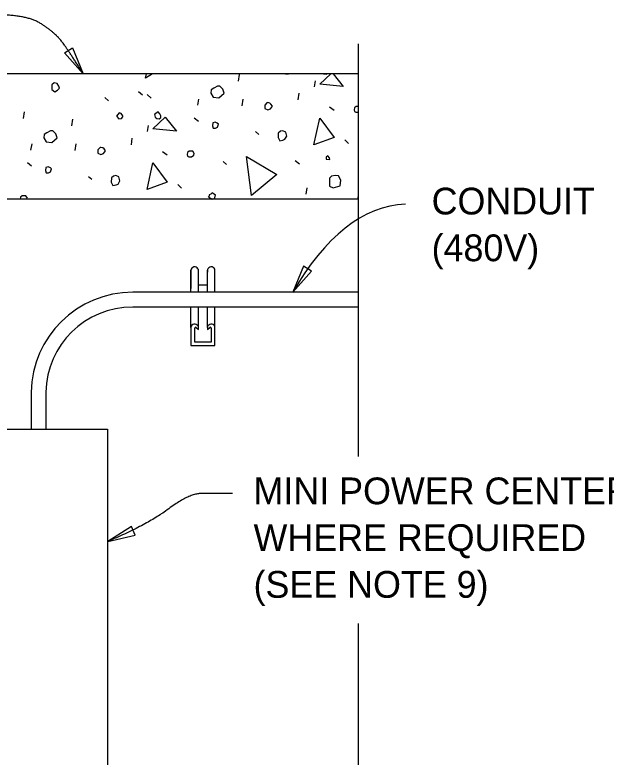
# Model space of a CAD drawing. Extents: x -1660015.2 to -1659984.9, y 2580594.2 to 2580616.7.
# Drawn here: x -1659999.271 to -1659995.935, y 2580610.338 to 2580614.529 of the extents above; entities that cross this region are included whole.
import ezdxf

# ---------------------------------------------------------------- set-up
doc = ezdxf.new("R2010")
doc.units = 0
for name, color, linetype in [('Default', 7, 'Continuous'), ('Miscellaneous', 7, 'Continuous'), ('Miscellaneous3', 7, 'Continuous'), ('SheetLines_dp', 7, 'Continuous')]:
    doc.layers.add(name, color=color, linetype=linetype)

msp = doc.modelspace()

# ---------------------------------------------------------------- linework, layer by layer
at = {"layer": 'Default'}
for p, q in [((-1659998.2775, 2580612.9626), (-1659998.2775, 2580613.0876)), ((-1659998.2775, 2580613.0876), (-1659998.2775, 2580612.985)), ((-1659998.2359, 2580613.092), (-1659998.238, 2580613.0958)), ((-1659998.2359, 2580613.0759), (-1659998.2359, 2580613.092)), ((-1659998.2359, 2580612.9626), (-1659998.2359, 2580613.0876)), ((-1659998.1816, 2580613.0958), (-1659998.1837, 2580613.092)), ((-1659998.1837, 2580613.092), (-1659998.1837, 2580613.0759)), ((-1659998.1837, 2580612.9626), (-1659998.1837, 2580613.0876)), ((-1659998.1421, 2580612.9626), (-1659998.1421, 2580613.0876)), ((-1659998.1837, 2580613.0037), (-1659998.2359, 2580613.0037)), ((-1659997.3318, 2580612.9626), (-1659998.6065, 2580612.9626)), ((-1659997.3318, 2580612.8794), (-1659998.6065, 2580612.8794)), ((-1659998.2775, 2580612.7647), (-1659998.2775, 2580612.8794)), ((-1659998.2359, 2580612.7647), (-1659998.2359, 2580612.8794)), ((-1659998.1837, 2580612.7647), (-1659998.1837, 2580612.8794)), ((-1659998.1421, 2580612.7647), (-1659998.1421, 2580612.8794)), ((-1659998.2359, 2580612.7691), (-1659998.238, 2580612.7729)), ((-1659998.2359, 2580612.753), (-1659998.2359, 2580612.7691)), ((-1659998.1816, 2580612.7729), (-1659998.1837, 2580612.7691)), ((-1659998.1837, 2580612.7691), (-1659998.1837, 2580612.753)), ((-1659998.2775, 2580612.7647), (-1659998.2775, 2580612.6621)), ((-1659998.2567, 2580612.6808), (-1659998.2567, 2580612.7604)), ((-1659998.2478, 2580612.7637), (-1659998.2359, 2580612.753)), ((-1659998.1837, 2580612.753), (-1659998.1718, 2580612.7637)), ((-1659998.1629, 2580612.7604), (-1659998.1629, 2580612.6808)), ((-1659998.1421, 2580612.6621), (-1659998.1421, 2580612.7647)), ((-1659998.2775, 2580612.6621), (-1659998.1421, 2580612.6621)), ((-1659998.1629, 2580612.6808), (-1659998.2567, 2580612.6808)), ((-1659999.1793, 2580612.3993), (-1659999.1793, 2580612.1902)), ((-1659999.096, 2580612.3985), (-1659999.096, 2580612.1902))]:
    msp.add_line(p, q, dxfattribs=at)
msp.add_lwpolyline([(-1659999.6133, 2580609.4652), (-1659999.7488, 2580609.4652), (-1659999.7488, 2580612.1902), (-1659998.7488, 2580612.1902), (-1659998.7488, 2580609.4652), (-1659998.8843, 2580609.4652)], dxfattribs=at)
for radius, end in [(0.5729, 179.0565), (0.4896, 178.9794)]:
    msp.add_arc((-1659998.6065, 2580612.3898), radius, 90, end, dxfattribs=at)
for centre, major_axis, start_param, end_param in [((-1659998.2567, 2580613.0876), (-0.0208, 0), 3.598509, 6.283184), ((-1659998.1629, 2580613.0876), (0.0208, 0), 0.000002, 2.684677), ((-1659998.2567, 2580612.7647), (-0.0208, 0), 3.598509, 6.283184), ((-1659998.1629, 2580612.7647), (0.0208, 0), 0.000002, 2.684677), ((-1659998.2515, 2580612.7604), (-0.0052, 0), 3.926991, 6.283185), ((-1659998.1681, 2580612.7604), (0.0052, 0), 6.283185, 8.63938)]:
    msp.add_ellipse(centre, major_axis=major_axis, ratio=0.8951, start_param=start_param, end_param=end_param, dxfattribs=at)
at = {"layer": 'Miscellaneous'}
for p, q in [((-1659998.281, 2580614.1961), (-1659998.2809, 2580614.197)), ((-1659998.0087, 2580614.1552), (-1659998.0032, 2580614.1929)), ((-1659997.5806, 2580614.1224), (-1659997.5745, 2580614.1577)), ((-1659998.5729, 2580614.0972), (-1659998.5519, 2580614.077)), ((-1659998.5241, 2580614.0792), (-1659998.5031, 2580614.059)), ((-1659997.6721, 2580614.0487), (-1659997.6667, 2580614.0864)), ((-1659998.7627, 2580614.0619), (-1659998.7424, 2580614.044)), ((-1659998.2386, 2580614.0186), (-1659998.2325, 2580614.0538)), ((-1659997.9893, 2580614.0155), (-1659997.9839, 2580614.0532)), ((-1659997.4962, 2580614.0104), (-1659997.4704, 2580613.9915)), ((-1659999.2228, 2580613.9438), (-1659999.2174, 2580613.9815)), ((-1659998.2587, 2580613.9485), (-1659998.2353, 2580613.9289)), ((-1659998.9504, 2580613.9029), (-1659998.945, 2580613.9406)), ((-1659998.5224, 2580613.8701), (-1659998.5163, 2580613.9053)), ((-1659997.9141, 2580613.87), (-1659997.8944, 2580613.8545)), ((-1659998.6139, 2580613.7964), (-1659998.6085, 2580613.834)), ((-1659997.41, 2580613.8239), (-1659997.389, 2580613.8036)), ((-1659999.1804, 2580613.7662), (-1659999.1743, 2580613.8015)), ((-1659998.9311, 2580613.7631), (-1659998.9257, 2580613.8008)), ((-1659998.438, 2580613.7581), (-1659998.4122, 2580613.7391)), ((-1659999.2004, 2580613.6961), (-1659999.1771, 2580613.6765)), ((-1659998.0969, 2580613.702), (-1659998.0765, 2580613.6841)), ((-1659997.6894, 2580613.7076), (-1659997.6661, 2580613.688)), ((-1659998.8559, 2580613.6176), (-1659998.8362, 2580613.6022)), ((-1659998.3518, 2580613.5715), (-1659998.3308, 2580613.5513)), ((-1659997.628, 2580613.517), (-1659997.6219, 2580613.5523))]:
    msp.add_line(p, q, dxfattribs=at)
for points in [[(-1659998.5335, 2580614.1725), (-1659998.5282, 2580614.197)], [(-1659998.4953, 2580614.197), (-1659998.5335, 2580614.1725)], [(-1659997.744, 2580614.197), (-1659997.7425, 2580614.1955), (-1659997.7274, 2580614.197), (-1659997.7273, 2580614.197)], [(-1659997.5511, 2580614.1381), (-1659997.4877, 2580614.197)], [(-1659997.4755, 2580614.197), (-1659997.4181, 2580614.1245), (-1659997.5511, 2580614.1381)], [(-1659997.5291, 2580614.197), (-1659997.5278, 2580614.1961), (-1659997.5145, 2580614.1945), (-1659997.5116, 2580614.197)], [(-1659999.0621, 2580614.1266), (-1659999.0624, 2580614.1084), (-1659999.0458, 2580614.0947), (-1659999.0302, 2580614.1041), (-1659999.0201, 2580614.1146), (-1659999.0233, 2580614.1266), (-1659999.0327, 2580614.1422), (-1659999.0491, 2580614.1456), (-1659999.0617, 2580614.1345), (-1659999.0621, 2580614.1266)], [(-1659998.1664, 2580614.0871), (-1659998.1527, 2580614.0649), (-1659998.1205, 2580614.0606), (-1659998.0912, 2580614.0865), (-1659998.0977, 2580614.1107), (-1659998.1149, 2580614.1268), (-1659998.1276, 2580614.1259), (-1659998.1481, 2580614.1153), (-1659998.1637, 2580614.1059), (-1659998.1664, 2580614.0871)], [(-1659997.8608, 2580614.0188), (-1659997.8611, 2580614.0006), (-1659997.8434, 2580613.9925), (-1659997.8296, 2580613.9988), (-1659997.8183, 2580614.0147), (-1659997.8264, 2580614.0255), (-1659997.8331, 2580614.0314), (-1659997.8441, 2580614.0337), (-1659997.8489, 2580614.0324), (-1659997.8608, 2580614.0188)], [(-1659997.3318, 2580614.012), (-1659997.3465, 2580614.0117), (-1659997.3548, 2580614.0043), (-1659997.3571, 2580613.9934), (-1659997.3545, 2580613.9837)], [(-1659998.6985, 2580613.9575), (-1659998.6843, 2580613.9431), (-1659998.6692, 2580613.9446), (-1659998.6614, 2580613.9544), (-1659998.6627, 2580613.9593), (-1659998.6714, 2580613.9725), (-1659998.683, 2580613.9771), (-1659998.6908, 2580613.9673), (-1659998.6985, 2580613.9575)], [(-1659998.4929, 2580613.8857), (-1659998.4224, 2580613.9512), (-1659998.3599, 2580613.8722), (-1659998.4929, 2580613.8857)], [(-1659998.4795, 2580613.9514), (-1659998.4696, 2580613.9437), (-1659998.4563, 2580613.9421), (-1659998.4479, 2580613.9495), (-1659998.4481, 2580613.9598), (-1659998.4537, 2580613.9713), (-1659998.4618, 2580613.9821), (-1659998.475, 2580613.9733), (-1659998.4833, 2580613.9659), (-1659998.4795, 2580613.9514)], [(-1659997.5836, 2580613.7955), (-1659997.5515, 2580613.9464), (-1659997.4702, 2580613.8362), (-1659997.5836, 2580613.7955)], [(-1659997.3545, 2580613.9837), (-1659997.3484, 2580613.9802), (-1659997.3326, 2580613.9792), (-1659997.3318, 2580613.9799)], [(-1659998.156, 2580613.9035), (-1659998.1522, 2580613.889), (-1659998.1394, 2580613.8898), (-1659998.128, 2580613.8955), (-1659998.1222, 2580613.9126), (-1659998.129, 2580613.9185), (-1659998.1406, 2580613.9232), (-1659998.1551, 2580613.9193), (-1659998.156, 2580613.9035)], [(-1659999.1082, 2580613.8347), (-1659999.0945, 2580613.8125), (-1659999.0622, 2580613.8082), (-1659999.033, 2580613.8342), (-1659999.0394, 2580613.8583), (-1659999.0567, 2580613.8744), (-1659999.0694, 2580613.8736), (-1659999.0899, 2580613.8629), (-1659999.1055, 2580613.8536), (-1659999.1082, 2580613.8347)], [(-1659997.7848, 2580613.8606), (-1659997.7862, 2580613.837), (-1659997.7762, 2580613.8189), (-1659997.7587, 2580613.821), (-1659997.7472, 2580613.8267), (-1659997.7366, 2580613.8451), (-1659997.7424, 2580613.8668), (-1659997.7602, 2580613.875), (-1659997.7722, 2580613.8718), (-1659997.7848, 2580613.8606)], [(-1659998.8026, 2580613.7665), (-1659998.8029, 2580613.7483), (-1659998.7852, 2580613.7401), (-1659998.7713, 2580613.7464), (-1659998.7601, 2580613.7624), (-1659998.7681, 2580613.7731), (-1659998.7749, 2580613.7791), (-1659998.7859, 2580613.7813), (-1659998.7907, 2580613.78), (-1659998.8026, 2580613.7665)], [(-1659998.2963, 2580613.7313), (-1659998.2901, 2580613.7278), (-1659998.2743, 2580613.7269), (-1659998.2618, 2580613.738), (-1659998.2589, 2580613.7465), (-1659998.2676, 2580613.7597), (-1659998.2882, 2580613.7594), (-1659998.2966, 2580613.752), (-1659998.2988, 2580613.741), (-1659998.2963, 2580613.7313)], [(-1659997.5155, 2580613.7154), (-1659997.4943, 2580613.7133), (-1659997.4968, 2580613.723), (-1659997.5049, 2580613.7337), (-1659997.5157, 2580613.7257), (-1659997.5155, 2580613.7154)], [(-1659998.5253, 2580613.5431), (-1659998.4933, 2580613.6941), (-1659998.412, 2580613.5839), (-1659998.5253, 2580613.5431)], [(-1659997.9365, 2580613.5094), (-1659997.9645, 2580613.7297), (-1659997.7924, 2580613.6282), (-1659997.9365, 2580613.5094)], [(-1659999.0978, 2580613.6512), (-1659999.0939, 2580613.6367), (-1659999.0812, 2580613.6375), (-1659999.0698, 2580613.6431), (-1659999.064, 2580613.6602), (-1659999.0708, 2580613.6662), (-1659999.0824, 2580613.6708), (-1659999.0969, 2580613.6669), (-1659999.0978, 2580613.6512)], [(-1659998.7266, 2580613.6083), (-1659998.728, 2580613.5846), (-1659998.718, 2580613.5666), (-1659998.7004, 2580613.5687), (-1659998.689, 2580613.5743), (-1659998.6784, 2580613.5927), (-1659998.6842, 2580613.6145), (-1659998.7019, 2580613.6226), (-1659998.714, 2580613.6194), (-1659998.7266, 2580613.6083)], [(-1659997.4967, 2580613.6065), (-1659997.4954, 2580613.5629), (-1659997.4746, 2580613.5529), (-1659997.4625, 2580613.5562), (-1659997.4359, 2580613.5633), (-1659997.4316, 2580613.5955), (-1659997.446, 2580613.6201), (-1659997.4648, 2580613.6228), (-1659997.4842, 2580613.6177), (-1659997.4967, 2580613.6065)], [(-1659998.1771, 2580613.4993), (-1659998.1588, 2580613.4887), (-1659998.1443, 2580613.4925), (-1659998.1391, 2580613.512), (-1659998.1582, 2580613.5251), (-1659998.1665, 2580613.5176), (-1659998.1755, 2580613.5126), (-1659998.1771, 2580613.4993), (-1659998.1784, 2580613.5041)], [(-1659999.2026, 2580613.4886), (-1659999.2007, 2580613.4942), (-1659999.2094, 2580613.5074), (-1659999.23, 2580613.507), (-1659999.2384, 2580613.4996), (-1659999.2406, 2580613.4887), (-1659999.2406, 2580613.4886)], [(-1659997.3359, 2580613.4886), (-1659997.3318, 2580613.5074)]]:
    msp.add_lwpolyline(points, dxfattribs=at)
at = {"layer": 'Miscellaneous3'}
for p, q in [((-1659997.3318, 2580614.197), (-1660002.3746, 2580614.197)), ((-1659997.3318, 2580613.4886), (-1660002.3746, 2580613.4886))]:
    msp.add_line(p, q, dxfattribs=at)
at = {"layer": 'SheetLines_dp'}
for points in [[(-1659997.3318, 2580612.0361), (-1659997.3318, 2580614.3666)], [(-1659997.3318, 2580605.4823), (-1659997.3318, 2580609.9205), (-1659997.4093, 2580609.9205), (-1659997.3318, 2580609.9542), (-1659997.2543, 2580609.988), (-1659997.3318, 2580609.988), (-1659997.3318, 2580611.0927)]]:
    msp.add_lwpolyline(points, dxfattribs=at)
for points in [[(-1659998.8861, 2580614.1969), (-1659998.9908, 2580614.3158), (-1659998.9457, 2580614.3437)], [(-1659997.7024, 2580612.9627), (-1659997.5977, 2580613.0816), (-1659997.6428, 2580613.1094)], [(-1659998.7469, 2580611.5561), (-1659998.5926, 2580611.592), (-1659998.6131, 2580611.6408)]]:
    msp.add_lwpolyline(points, close=True, dxfattribs=at)
msp.add_ellipse((-1659996.9572, 2580611.0938), major_axis=(0.1111, -2.3674), ratio=0.464296, start_param=3.141604, end_param=3.781128, dxfattribs=at)
for points in [[(-1659998.8861, 2580614.197), (-1659998.9683, 2580614.3298), (-1659999.0489, 2580614.4326), (-1659999.204, 2580614.5295), (-1659999.3716, 2580614.5295)], [(-1659998.0426, 2580611.8267), (-1659998.1498, 2580611.8267), (-1659998.2876, 2580611.8267), (-1659998.5275, 2580611.648), (-1659998.7469, 2580611.5561)]]:
    msp.add_open_spline(points, degree=2, dxfattribs=at)

# ---------------------------------------------------------------- texts
for s, p in [('CONDUIT', (-1659996.92, 2580613.4023)), ('(480V)', (-1659996.92, 2580613.1383)), ('MINI POWER CENTER', (-1659997.9246, 2580611.7658)), ('WHERE REQUIRED', (-1659997.9246, 2580611.5018)), ('(SEE NOTE 9)', (-1659997.9246, 2580611.2378))]:
    msp.add_text(s, height=0.1512, dxfattribs=at).set_placement(p)

doc.saveas('drawing.dxf')
